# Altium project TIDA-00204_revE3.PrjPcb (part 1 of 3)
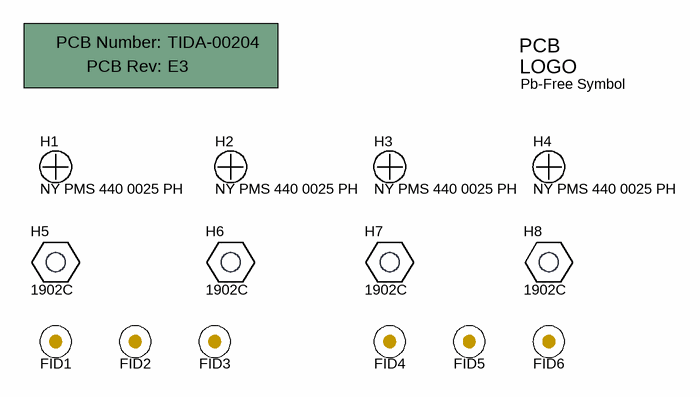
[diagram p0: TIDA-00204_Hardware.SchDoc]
CopyrightYear: 2017; EVM_Orderable: N/A; PCB_Layout: Klaus Hacker; PCB_Rev: E3; PRJ_Customer: TI Confidential - NDA; PRJ_Engineer: Texas Instruments; PRJ_Number: TIDA-00204; PRJ_Title: EMI Compliant Dual Port Industrial Gigabit Ethernet PHY; SCH_Rev: E3; TechSupport: http://www.ti.com/support
10 sheets, 537 parts. Net scope: global (net labels, ports and power ports of the same name join across sheets).
Board file: TIDA-00204_revE3_PCB.PcbDoc
Sheets:
  TIDA-00204_Hardware.SchDoc
  TIDA-00204_revE3_JTAGUSB.SchDoc
  TIDA-00204_revE3_Memory.SchDoc
  TIDA-00204_revE3_PHY_1.SchDoc
  TIDA-00204_revE3_PHY_2.SchDoc
  TIDA-00204_revE3_PS_0.SchDoc
  TIDA-00204_revE3_PS_1.SchDoc
  TIDA-00204_revE3_PS_2.SchDoc
  TIDA-00204_revE3_Sitara_PS.SchDoc
  TIDA-00204_revE3_Sitara_SC_0.SchDoc

## Sheet TIDA-00204_Hardware.SchDoc: =DocumentName
size 431 x 279 mm; Date: Not shown in title block; ApprovedBy: Not shown in title block; CheckedBy: Not shown in title block; Author: Not shown in title block; CompanyName: Not shown in title block; DrawnBy: K. Mogensen; Engineer: K. Mogensen; Organization: Not shown in title block; Address1: Not shown in title block; Address2: Not shown in title block; Address3: Not shown in title block; Address4: Not shown in title block; DocumentNumber: 10; Revision: Use project parameter SCH_Rev; SheetNumber: 10; SheetTotal: 10; PageSetup: Record=PageOptions¦CenterHorizontal=True¦CenterVertical=True¦PrintScale=1.00¦XCorrection=1.00¦YCorrection=1.00¦PrintKind=0¦BorderSize=5000000¦LeftOffset=0¦BottomOffset=0¦Orientation=2¦PaperLength=1000¦PaperWidth=1000¦Scale=100¦PaperSource=15¦PrintQuality=600¦MediaType=1¦DitherType=10¦PaperKind=Letter¦PrintScaleMode=1

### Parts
!PCB1  Printed Circuit Board  (value not drawn)  (mechanical)
FID1  Fiducial  [Fiducial10-20]  (value not drawn)  (no BOM)
FID2  Fiducial  [Fiducial10-20]  (value not drawn)  (no BOM)
FID3  Fiducial  [Fiducial10-20]  (value not drawn)  (no BOM)
FID4  Fiducial  [Fiducial10-20]  (value not drawn)  (no BOM)
FID5  Fiducial  [Fiducial10-20]  (value not drawn)  (no BOM)
FID6  Fiducial  [Fiducial10-20]  (value not drawn)  (no BOM)
H1  NY PMS 440 0025 PH  [NY PMS 440 0025 PH]
H2  NY PMS 440 0025 PH  [NY PMS 440 0025 PH]
H3  NY PMS 440 0025 PH  [NY PMS 440 0025 PH]
H4  NY PMS 440 0025 PH  [NY PMS 440 0025 PH]
H5  1902C  [Keystone_1902C]
H6  1902C  [Keystone_1902C]
H7  1902C  [Keystone_1902C]
H8  1902C  [Keystone_1902C]
Logo2  Pb-Free Symbol  [Pb-Free_Overlay_Small]  (no BOM)

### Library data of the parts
!PCB1 = PCB: Manufacturer: Any; PartNumber: TIDA-00204; SymbolCreator: a0412235
FID1-FID6 = Fiducial: Fiducial mark.  There is nothing to buy or mount.; SymbolCreator: codlsc
H1-H4 = NY PMS 440 0025 PH: Machine Screw, Round, #4-40 x 1/4, Nylon, Philips panhead; Manufacturer: B&F Fastener Supply; CompType: Hardware; SymbolCreator: codlsc; U/M: EA
H5-H8 = 1902C: Standoff, Hex, 0.5"L #4-40 Nylon; Manufacturer: Keystone; CompType: Hardware
Logo2 = Pb-Free: SymbolCreator: a0412235

## Sheet TIDA-00204_revE3_JTAGUSB.SchDoc: =DocumentName
size 431 x 279 mm; Date: Not shown in title block; ApprovedBy: Not shown in title block; CheckedBy: Not shown in title block; Author: Not shown in title block; CompanyName: Not shown in title block; DrawnBy: K. Mogensen; Engineer: K. Mogensen; Organization: Not shown in title block; Address1: Not shown in title block; Address2: Not shown in title block; Address3: Not shown in title block; Address4: Not shown in title block; DocumentNumber: 9; Revision: Use project parameter SCH_Rev; SheetNumber: 9; SheetTotal: 10; PageSetup: Record=PageOptions¦CenterHorizontal=True¦CenterVertical=True¦PrintScale=0.62¦XCorrection=1.00¦YCorrection=1.00¦PrintKind=0¦BorderSize=5000000¦LeftOffset=0¦BottomOffset=0¦Orientation=2¦PaperLength=1000¦PaperWidth=1000¦Scale=100¦PaperSource=15¦PrintQuality=600¦MediaType=1¦DitherType=10¦PaperKind=Letter¦PrintScaleMode=1
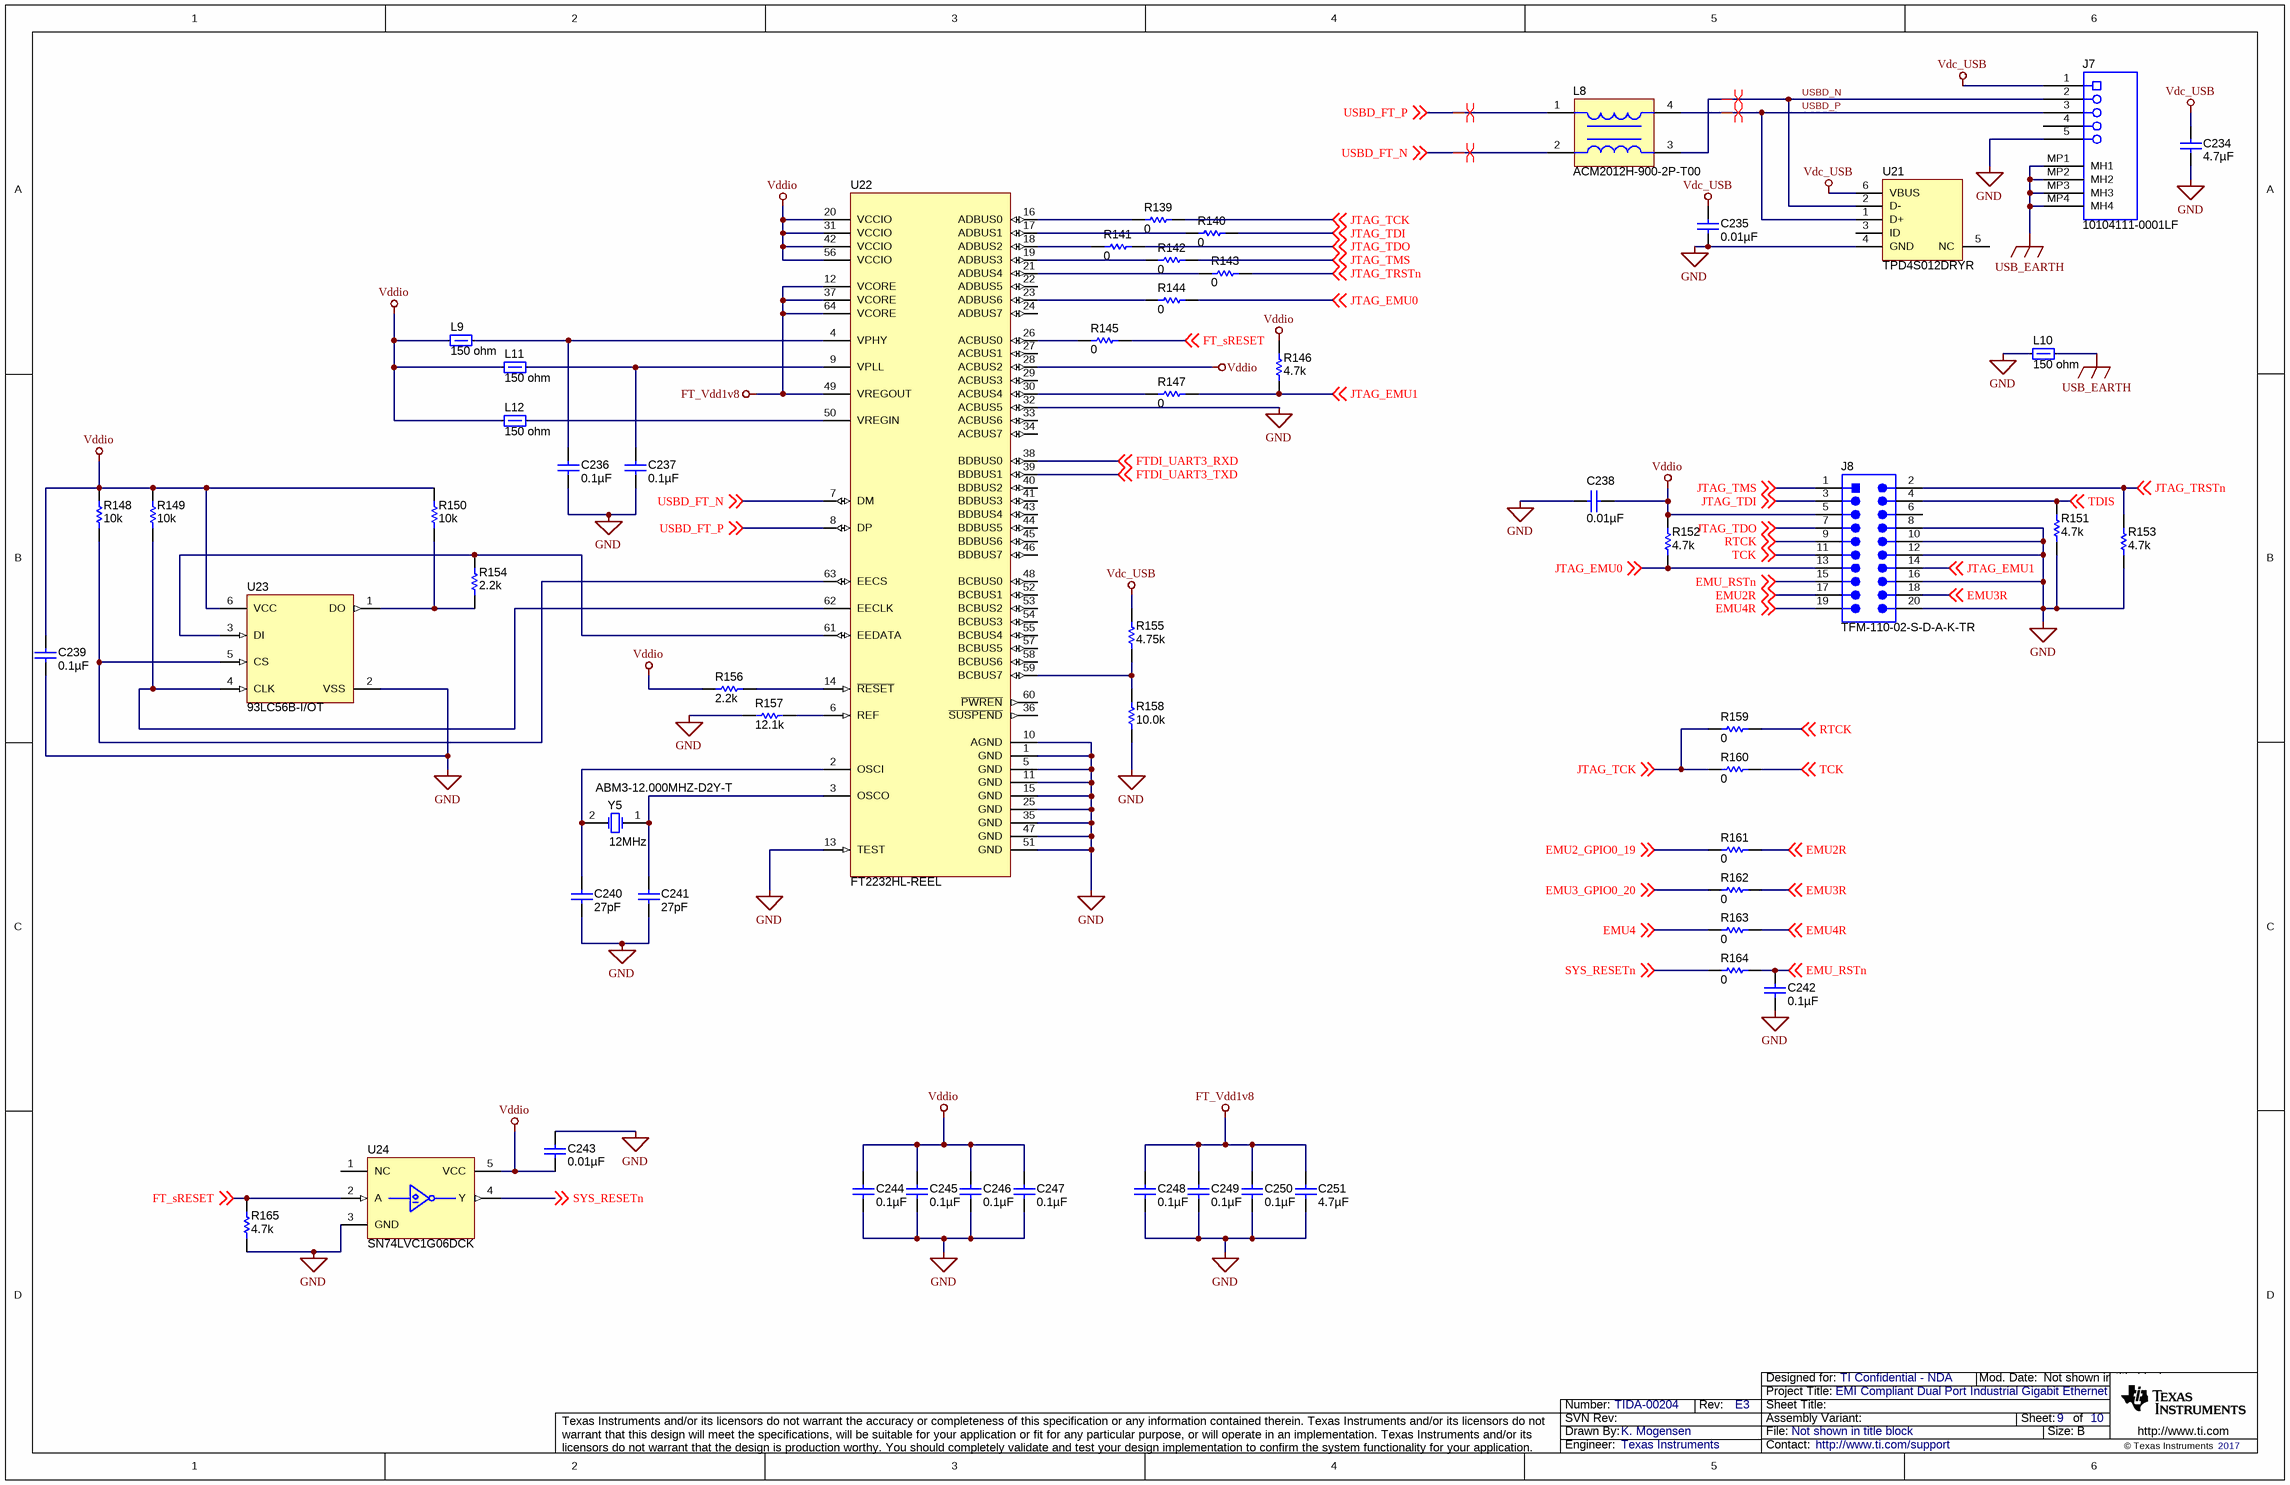
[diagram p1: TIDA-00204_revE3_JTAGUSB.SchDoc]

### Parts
C234  ValueDisplayed: 4.7µF  [0603]  (hidden comment: GRM188R61C475KAAJ)
C235  ValueDisplayed: 0.01µF  [0201]  (hidden comment: GRM033R71A103KA01D)
C236  ValueDisplayed: 0.1µF  [0402]  (hidden comment: GRM155R71A104KA01D)
C237  ValueDisplayed: 0.1µF  [0402]  (hidden comment: GRM155R71A104KA01D)
C238  ValueDisplayed: 0.01µF  [0201]  (hidden comment: GRM033R71A103KA01D)
C239  ValueDisplayed: 0.1µF  [0402]  (hidden comment: GRM155R71A104KA01D)
C240  ValueDisplayed: 27pF  [0402]  (hidden comment: GRM1555C1H270JA01D)
C241  ValueDisplayed: 27pF  [0402]  (hidden comment: GRM1555C1H270JA01D)
C242  ValueDisplayed: 0.1µF  [0402]  (hidden comment: GRM155R71A104KA01D)
C243  ValueDisplayed: 0.01µF  [0201]  (hidden comment: GRM033R71A103KA01D)
C244  ValueDisplayed: 0.1µF  [0402]  (hidden comment: GRM155R71A104KA01D)
C245  ValueDisplayed: 0.1µF  [0402]  (hidden comment: GRM155R71A104KA01D)
C246  ValueDisplayed: 0.1µF  [0402]  (hidden comment: GRM155R71A104KA01D)
C247  ValueDisplayed: 0.1µF  [0402]  (hidden comment: GRM155R71A104KA01D)
C248  ValueDisplayed: 0.1µF  [0402]  (hidden comment: GRM155R71A104KA01D)
C249  ValueDisplayed: 0.1µF  [0402]  (hidden comment: GRM155R71A104KA01D)
C250  ValueDisplayed: 0.1µF  [0402]  (hidden comment: GRM155R71A104KA01D)
C251  ValueDisplayed: 4.7µF  [0603]  (hidden comment: GRM188R61C475KAAJ)
J7  10104111-0001LF  [FCI_10104111-0001LF]
J8  TFM-110-02-S-D-A-K-TR  [Samtec_TFM-110-02-S-D-A-K]
L8  ACM2012H-900-2P-T00  [TDK_ACM2012H-900-2P-T00]
L9  value 150 ohm  [0805_HV]  (hidden comment: LI0805H151R-10)
L10  value 150 ohm  [0805_HV]  (hidden comment: LI0805H151R-10)
L11  value 150 ohm  [0805_HV]  (hidden comment: LI0805H151R-10)
L12  value 150 ohm  [0805_HV]  (hidden comment: LI0805H151R-10)
R139  ValueDisplayed: 0  [0603]  (hidden comment: CRCW06030000Z0EA)
R140  ValueDisplayed: 0  [0603]  (hidden comment: CRCW06030000Z0EA)
R141  ValueDisplayed: 0  [0603]  (hidden comment: CRCW06030000Z0EA)
R142  ValueDisplayed: 0  [0603]  (hidden comment: CRCW06030000Z0EA)
R143  ValueDisplayed: 0  [0603]  (hidden comment: CRCW06030000Z0EA)
R144  ValueDisplayed: 0  [0603]  (hidden comment: CRCW06030000Z0EA)
R145  ValueDisplayed: 0  [0603]  (hidden comment: CRCW06030000Z0EA)
R146  ValueDisplayed: 4.7k  [0402]  (hidden comment: CRCW04024K70JNED)
R147  ValueDisplayed: 0  [0603]  (hidden comment: CRCW06030000Z0EA)
R148  ValueDisplayed: 10k  [0402]  (hidden comment: CRCW040210K0JNED)
R149  ValueDisplayed: 10k  [0402]  (hidden comment: CRCW040210K0JNED)
R150  ValueDisplayed: 10k  [0402]  (hidden comment: CRCW040210K0JNED)
R151  ValueDisplayed: 4.7k  [0402]  (hidden comment: CRCW04024K70JNED)
R152  ValueDisplayed: 4.7k  [0402]  (hidden comment: CRCW04024K70JNED)
R153  ValueDisplayed: 4.7k  [0402]  (hidden comment: CRCW04024K70JNED)
R154  ValueDisplayed: 2.2k  [0402]  (hidden comment: CRCW04022K20JNED)
R155  ValueDisplayed: 4.75k  [0402]  (hidden comment: CRCW04024K75FKED)
R156  ValueDisplayed: 2.2k  [0402]  (hidden comment: CRCW04022K20JNED)
R157  ValueDisplayed: 12.1k  [0402]  (hidden comment: CRCW040212K1FKED)
R158  ValueDisplayed: 10.0k  [0402]  (hidden comment: CRCW040210K0FKED)
R159  ValueDisplayed: 0  [0603]  (hidden comment: CRCW06030000Z0EA)
R160  ValueDisplayed: 0  [0603]  (hidden comment: CRCW06030000Z0EA)
R161  ValueDisplayed: 0  [0603]  (hidden comment: CRCW06030000Z0EA)
R162  ValueDisplayed: 0  [0603]  (hidden comment: CRCW06030000Z0EA)
R163  ValueDisplayed: 0  [0603]  (hidden comment: CRCW06030000Z0EA)
R164  ValueDisplayed: 0  [0603]  (hidden comment: CRCW06030000Z0EA)
R165  ValueDisplayed: 4.7k  [0402]  (hidden comment: CRCW04024K70JNED)
U21  TPD4S012DRYR  [DRY0006A]
U22  FT2232HL-REEL  [LQFP64_N]
U23  93LC56B-I/OT  [SOT-23-6]
U24  SN74LVC1G06DCK  [DCK0005A_N]
Y5  ABM3-12.000MHZ-D2Y-T  Frequency: 12MHz  [XTAL_ABM3]

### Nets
FT_Vdd1v8: C248.2 C249.2 C250.2 C251.1 U22.12(VCORE) U22.37(VCORE) U22.49(VREGOUT) U22.64(VCORE)
GND: C234.2 C235.2 C236.1 C237.1 C238.1 C239.1 C240.2 C241.2 C242.1 C243.1 C244.1 C245.1 C246.1 C247.1 C248.1 C249.1 C250.1 C251.2 J7.5 J8.8 J8.10 J8.12 J8.16 J8.20 L10.1 R151.1 R153.1 R157.1 R158.1 R165.1 U21.4(GND) U22.1(GND) U22.5(GND) U22.10(AGND) U22.11(GND) U22.13(TEST) U22.15(GND) U22.25(GND) U22.32(ACBUS5) U22.35(GND) U22.47(GND) U22.51(GND) U23.2(VSS) U24.3(GND)
USB_EARTH: J7.MP1(MH1) J7.MP2(MH2) J7.MP3(MH3) J7.MP4(MH4) L10.2
Vdc_USB: C234.1 C235.1 J7.1 R155.2 U21.6(VBUS)
Vddio: C238.2 C239.2 C243.2 C244.2 C245.2 C246.2 C247.2 J8.5 L9.1 L11.1 L12.1 R146.2 R148.2 R149.2 R150.2 R152.2 R156.2 U22.20(VCCIO) U22.28(ACBUS2) U22.31(VCCIO) U22.42(VCCIO) U22.56(VCCIO) U23.6(VCC) U24.5(VCC)
EMU2_GPIO0_19: R161.1 ; off-sheet EMU2_GPIO0_19
EMU2R: J8.17 R161.2 ; off-sheet EMU2R
EMU3_GPIO0_20: R162.1 ; off-sheet EMU3_GPIO0_20
EMU3R: J8.18 R162.2 ; off-sheet EMU3R
EMU4: R163.1 ; off-sheet EMU4
EMU4R: J8.19 R163.2 ; off-sheet EMU4R
EMU_RSTn: C242.2 J8.15 R164.2 ; off-sheet EMU_RSTn
FT_sRESET: R145.2 R165.2 U24.2(A) ; off-sheet FT_sRESET
FTDI_UART3_RXD: U22.38(BDBUS0) ; off-sheet FTDI_UART3_RXD
FTDI_UART3_TXD: U22.39(BDBUS1) ; off-sheet FTDI_UART3_TXD
JTAG_EMU0: J8.13 R144.2 R152.1 ; off-sheet JTAG_EMU0
JTAG_EMU1: J8.14 R146.1 R147.2 ; off-sheet JTAG_EMU1
JTAG_TCK: R139.2 R159.1 R160.1 ; off-sheet JTAG_TCK
JTAG_TDI: J8.3 R140.2 ; off-sheet JTAG_TDI
JTAG_TDO: J8.7 R141.2 ; off-sheet JTAG_TDO
JTAG_TMS: J8.1 R142.2 ; off-sheet JTAG_TMS
JTAG_TRSTn: J8.2 R143.2 R153.2 ; off-sheet JTAG_TRSTn
RTCK: J8.9 R159.2 ; off-sheet RTCK
SYS_RESETn: R164.1 U24.4(Y) ; off-sheet SYS_RESETn
TCK: J8.11 R160.2 ; off-sheet TCK
TDIS: J8.4 R151.2 ; off-sheet TDIS
USBD_FT_N: L8.2 U22.7(DM) ; off-sheet USBD_FT_N
USBD_FT_P: L8.1 U22.8(DP) ; off-sheet USBD_FT_P
USBD_N: J7.2 L8.3 U21.2(D-)
USBD_P: J7.3 L8.4 U21.1(D+)
NetC236_2: C236.2 L9.2 U22.4(VPHY)
NetC237_2: C237.2 L11.2 U22.9(VPLL)
NetC240_1: C240.1 U22.2(OSCI) Y5.2(OSC2)
NetC241_1: C241.1 U22.3(OSCO) Y5.1(OSC1)
NetL12_2: L12.2 U22.50(VREGIN)
NetR139_1: R139.1 U22.16(ADBUS0)
NetR140_1: R140.1 U22.17(ADBUS1)
NetR141_1: R141.1 U22.18(ADBUS2)
NetR142_1: R142.1 U22.19(ADBUS3)
NetR143_1: R143.1 U22.21(ADBUS4)
NetR144_1: R144.1 U22.23(ADBUS6)
NetR145_1: R145.1 U22.26(ACBUS0)
NetR147_1: R147.1 U22.30(ACBUS4)
NetR148_1: R148.1 U22.63(EECS) U23.5(CS)
NetR149_1: R149.1 U22.62(EECLK) U23.4(CLK)
NetR150_1: R150.1 R154.1 U23.1(DO)
NetR154_2: R154.2 U22.61(EEDATA) U23.3(DI)
NetR155_1: R155.1 R158.2 U22.59(BCBUS7)
NetR156_1: R156.1 U22.14(~{RESET})
NetR157_2: R157.2 U22.6(REF)

Not connected (* = marked no-connect by the designer): J7 4; J8 6; U21 3(ID) 5(NC); U22 22(ADBUS5) 24(ADBUS7) 27(ACBUS1) 29(ACBUS3) 33(ACBUS6) 34(ACBUS7) 36(~{SUSPEND}) 40(BDBUS2) 41(BDBUS3) 43(BDBUS4) 44(BDBUS5) 45(BDBUS6) 46(BDBUS7) 48(BCBUS0) 52(BCBUS1) 53(BCBUS2) 54(BCBUS3) 55(BCBUS4) 57(BCBUS5) 58(BCBUS6) 60(~{PWREN}); U24 1(NC)

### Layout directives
differential pair: USBD_FT_N, USBD_FT_P, USBD_N, USBD_P

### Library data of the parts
C234 C251 = GRM188R61C475KAAJ: CAP, CERM, 4.7 µF, 16 V, +/- 10%, X5R, 0603; Manufacturer: MuRata; Polarized: N; CompType: Capacitor; Value: 4.7uF; U/M: EA; Cap_F: 0.0000047; Tolerance_%: 10; Value1: Unknown; VDC_V: 16; Value2: 16V; TaMin_C: -55; TaMax_C: 85
C235 C238 C243 = GRM033R71A103KA01D: CAP, CERM, 0.01 µF, 10 V, +/- 10%, X7R, 0201; Manufacturer: MuRata; Polarized: N; CompType: Capacitor; Value: 0.01uF; U/M: EA; Cap_F: 0.00000001; Tolerance_%: 10; Value1: Unknown; Value2: 10V; TaMin_C: -55; TaMax_C: 125
C236 C237 C239 C242 C244-C250 = GRM155R71A104KA01D: CAP, CERM, 0.1 µF, 10 V, +/- 10%, X7R, 0402; Manufacturer: MuRata; Polarized: N; CompType: Capacitor; Value: 0.1uF; U/M: EA; Cap_F: 0.0000001; Tolerance_%: 10; Value1: Unknown; Value2: 10V; TaMin_C: -55; TaMax_C: 125
C240 C241 = GRM1555C1H270JA01D: CAP, CERM, 27 pF, 50 V, +/- 5%, C0G/NP0, 0402; Manufacturer: MuRata; Polarized: N; CompType: Capacitor; Value: 27pF; U/M: EA; Cap_F: 0.000000000027; Tolerance_%: 5; Value1: Unknown; VDC_V: 50; Value2: 50V; TaMin_C: -55; TaMax_C: 125
J7 = 10104111-0001LF: Receptacle, 0.65 mm, 5x1, Gold, R/A, SMT; Manufacturer: FCI; SymbolCreator: Altium; U/M: EA
J8 = TFM-110-02-S-D-A-K-TR: CONN SHRD HDR HDR 20 POS 1.27MM SLDR ST SMD; Manufacturer: Samtec; SymbolCreator: a0412235; CompType: Header; U/M: EA
L8 = ACM2012H-900-2P-T00: Common Mode Filter, 90 Ohm, 6 GHz, SMD; Manufacturer: TDK; SymbolCreator: Altium; Value: 90Ohm
L9-L12 = LI0805H151R-10: Ferrite Bead, 150 ohm @ 100 MHz, 0.8 A, 0805; Manufacturer: Laird-Signal Integrity Products; Imax_A: 0.8; DCR_ohm: 0.15; Value1: 0.15 ohm; Value2: 0.8A; ZTyp@100MHz_Ohm: 150
R139-R145 R147 R159-R164 = CRCW06030000Z0EA: RES, 0, 5%, 0.1 W, 0603; Manufacturer: Vishay-Dale; CompType: Resistor; Value: 0; Value_Code: 0000; Tolerance_%: 5; Power_W: 0.1; Value2: 0.1W; VDC_V: 75; TempCo: 200 ppm/C; EIA_Code: E24; U/M: EA
R146 R151-R153 R165 = CRCW04024K70JNED: RES, 4.7 k, 5%, 0.063 W, 0402; Manufacturer: Vishay-Dale; CompType: Resistor; Value: 4.7k; Res_ohm: 4700; Value_Code: 4k70; Tolerance_%: 5; Power_W: 0.063; Value2: 0.063W; VDC_V: 50; TempCo: 200 ppm/C; EIA_Code: E24; U/M: EA
R148-R150 = CRCW040210K0JNED: RES, 10 k, 5%, 0.063 W, 0402; Manufacturer: Vishay-Dale; CompType: Resistor; Value: 10k; Res_ohm: 10000; Value_Code: 10k0; Tolerance_%: 5; Power_W: 0.063; Value2: 0.063W; VDC_V: 50; TempCo: 200 ppm/C; EIA_Code: E24; U/M: EA
R154 R156 = CRCW04022K20JNED: RES, 2.2 k, 5%, 0.063 W, 0402; Manufacturer: Vishay-Dale; CompType: Resistor; Value: 2.2k; Res_ohm: 2200; Value_Code: 2k20; Tolerance_%: 5; Power_W: 0.063; Value2: 0.063W; VDC_V: 50; TempCo: 200 ppm/C; EIA_Code: E24; U/M: EA
R155 = CRCW04024K75FKED: RES, 4.75 k, 1%, 0.063 W, 0402; Manufacturer: Vishay-Dale; CompType: Resistor; Value: 4.75k; Res_ohm: 4750; Value_Code: 4k75; Tolerance_%: 1; Power_W: 0.063; Value2: 0.063W; VDC_V: 50; TempCo: 100 ppm/C; EIA_Code: E96; U/M: EA
R157 = CRCW040212K1FKED: RES, 12.1 k, 1%, 0.063 W, 0402; Manufacturer: Vishay-Dale; CompType: Resistor; Value: 12.1k; Res_ohm: 12100; Value_Code: 12k1; Tolerance_%: 1; Power_W: 0.063; Value2: 0.063W; VDC_V: 50; TempCo: 100 ppm/C; EIA_Code: E96; U/M: EA
R158 = CRCW040210K0FKED: RES, 10.0 k, 1%, 0.063 W, 0402; Manufacturer: Vishay-Dale; CompType: Resistor; Value: 10.0k; Res_ohm: 10000; Value_Code: 10k0; Tolerance_%: 1; Power_W: 0.063; Value2: 0.063W; VDC_V: 50; TempCo: 100 ppm/C; EIA_Code: E96; U/M: EA
U21 = TPD4S012DRYR: USB ESD Solution with Power Clamp, 4 Channels, -40 to +85 degC, 6-pin SON (DRY), Green (RoHS & no Sb/Br); Manufacturer: Texas Instruments; Alternate Manufacturer: None; Alternate PartNumber: Equivalent; Breakdown Voltage(Min)(V): 6; IEC 61000-4-2 Air-Gap(+/- kV): 10; IO Capacitance(Typ)(pF): 0.8; USB High Speed: TRUE
U22 = FT2232HL-REEL: Dual High Speed USB To Multipurpose UART/FIFO IC, LQFP-64; Manufacturer: FTDI; SymbolCreator: Altium
U23 = 93LC56B-I/OT: 2K Microwire Compatible Serial EEPROM, SOT-23-6; Manufacturer: Microchip; SymbolCreator: x0208326
U24 = SN74LVC1G06DCK: Single Inverter Buffer/Driver With Open-Drain Output, DCK0005A; Alternate Manufacturer: None; Manufacturer: Texas Instruments; SymbolCreator: a0411947; CompType: IC; U/M: EA
Y5 = ABM3-12.000MHZ-D2Y-T: Crystal, 12 MHz, 18 pF, SMD; Manufacturer: Abracon Corportation; SymbolCreator: a0412235; U/M: EA; TaMin_C: -40; TaMax_C: 85; Frequency Stability: ±30ppm

## Sheet TIDA-00204_revE3_Memory.SchDoc: =DocumentName
size 431 x 279 mm; Date: Not shown in title block; ApprovedBy: Not shown in title block; CheckedBy: Not shown in title block; Author: Not shown in title block; CompanyName: Not shown in title block; DrawnBy: K. Mogensen; Engineer: K. Mogensen; Organization: Not shown in title block; Address1: Not shown in title block; Address2: Not shown in title block; Address3: Not shown in title block; Address4: Not shown in title block; DocumentNumber: 8; Revision: Use project parameter SCH_Rev; SheetNumber: 8; SheetTotal: 10; PageSetup: Record=PageOptions¦CenterHorizontal=True¦CenterVertical=True¦PrintScale=0.62¦XCorrection=1.00¦YCorrection=1.00¦PrintKind=0¦BorderSize=5000000¦LeftOffset=0¦BottomOffset=0¦Orientation=2¦PaperLength=1000¦PaperWidth=1000¦Scale=100¦PaperSource=15¦PrintQuality=600¦MediaType=1¦DitherType=10¦PaperKind=Letter¦PrintScaleMode=1
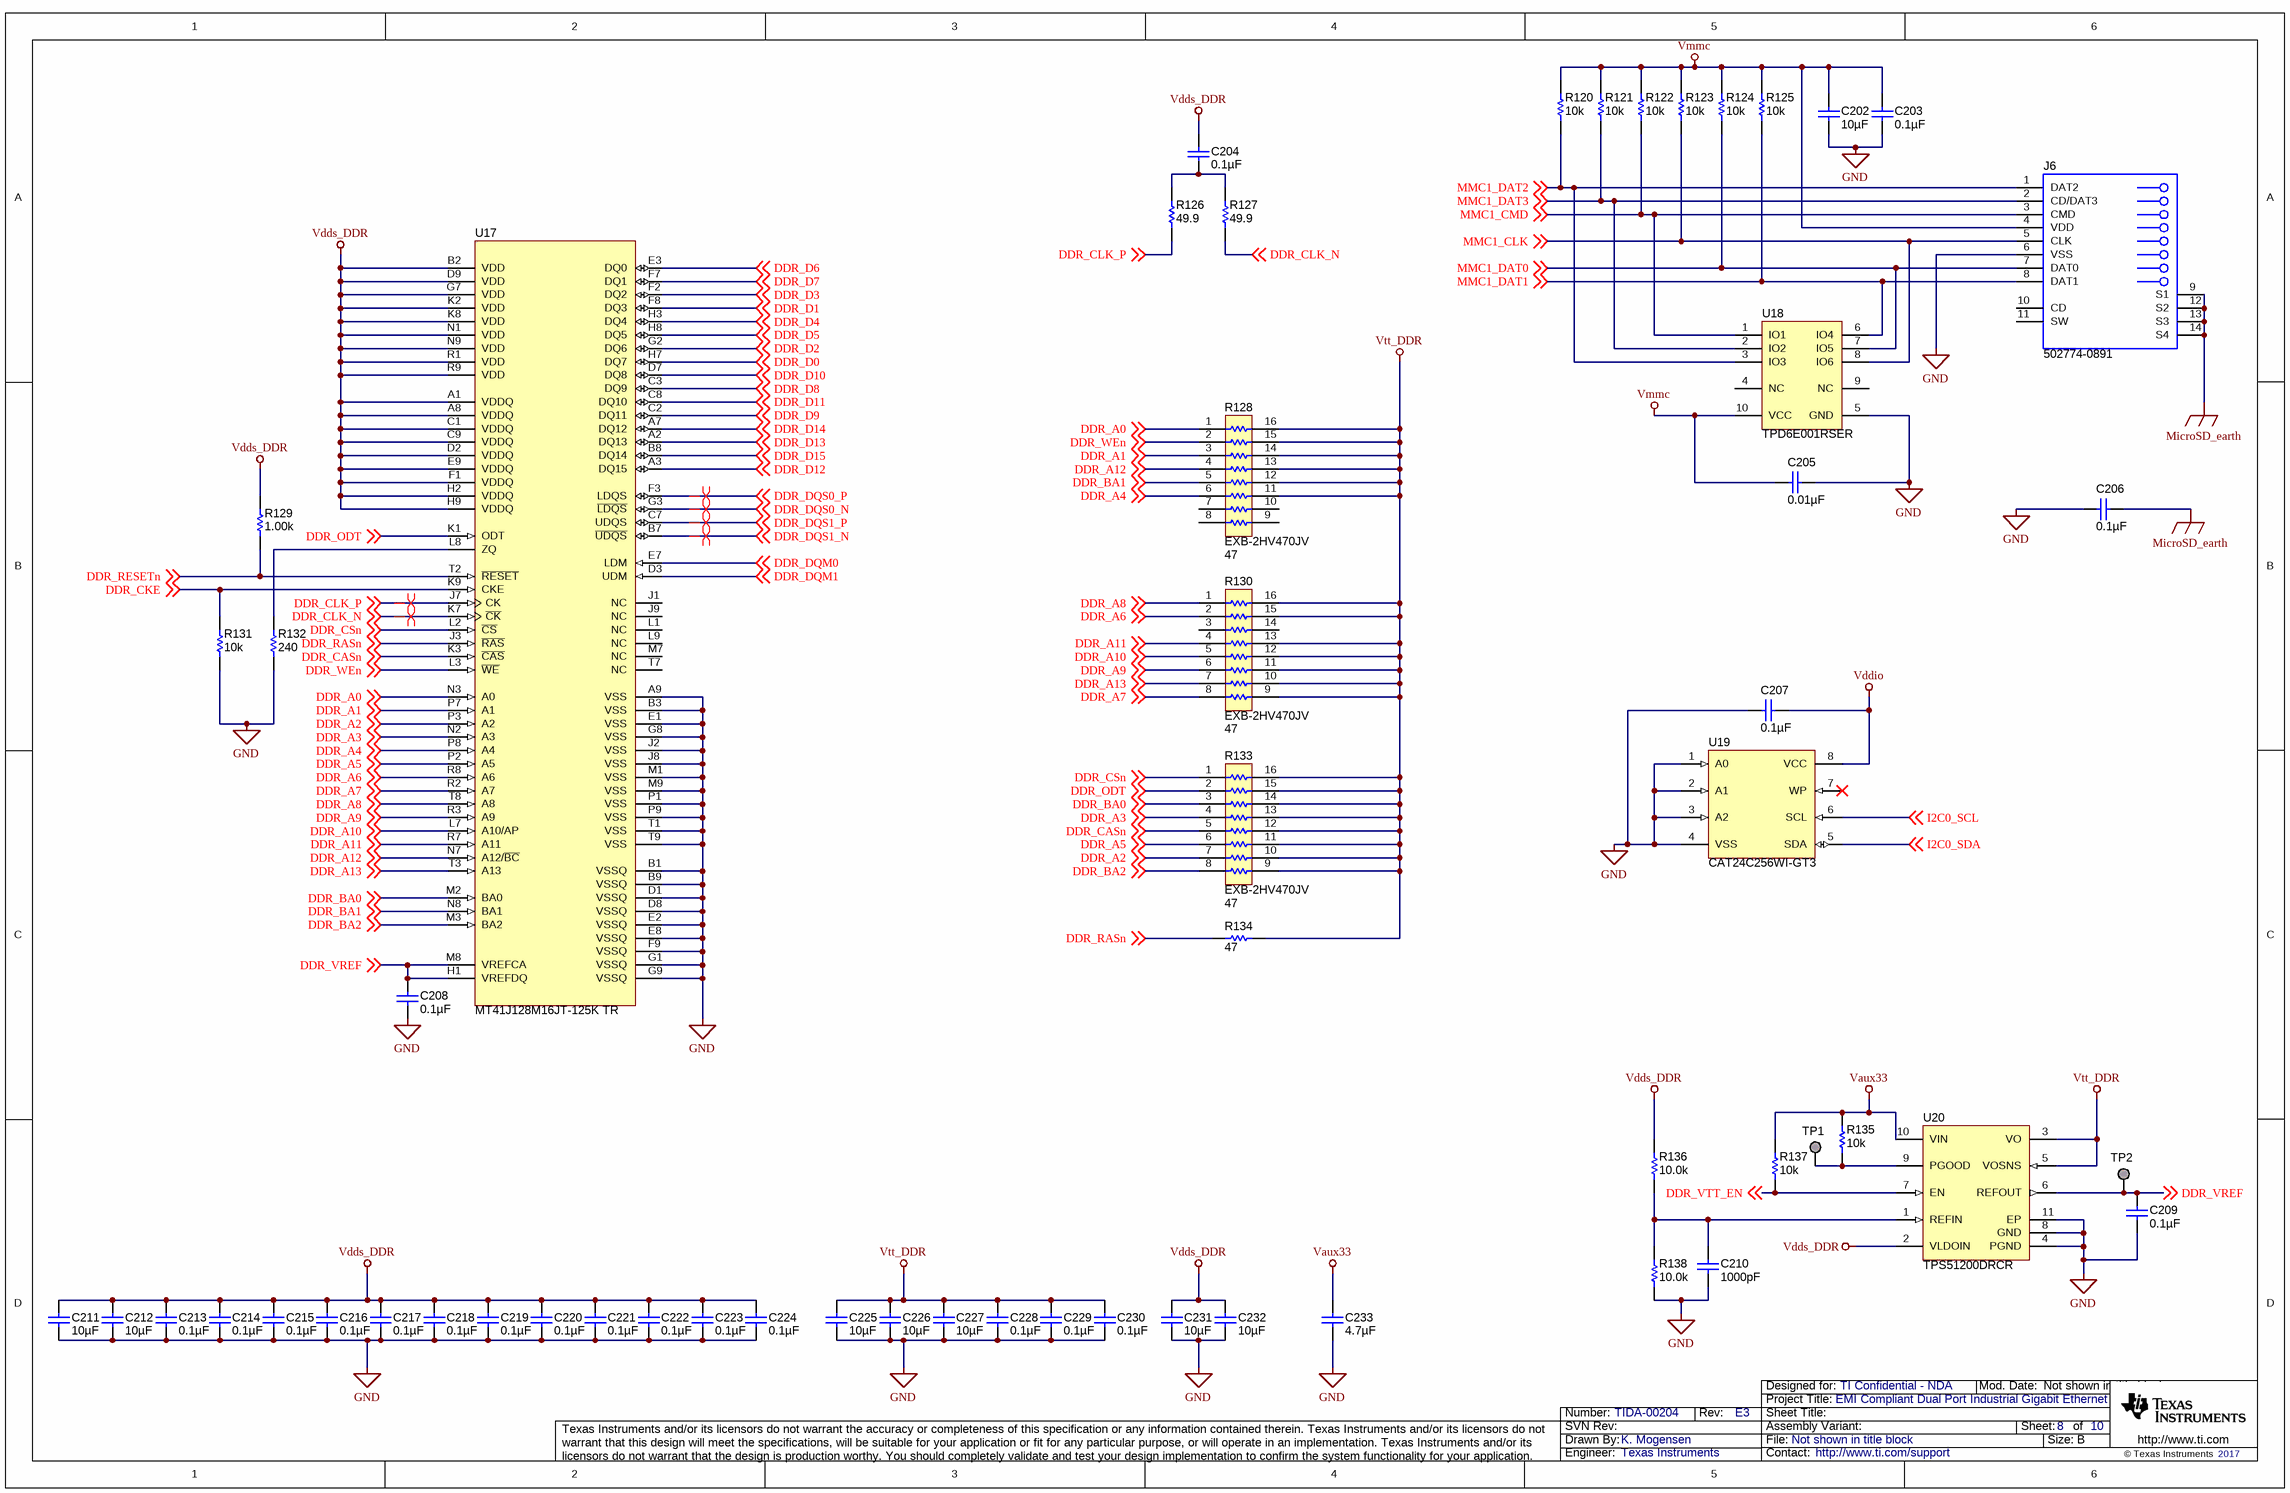
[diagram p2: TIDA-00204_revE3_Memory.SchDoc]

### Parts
C202  ValueDisplayed: 10µF  [0603]  (hidden comment: C1608X5R1E106M080AC)
C203  ValueDisplayed: 0.1µF  [0402]  (hidden comment: GRM155R71A104KA01D)
C204  ValueDisplayed: 0.1µF  [0402]  (hidden comment: GRM155R71A104KA01D)
C205  ValueDisplayed: 0.01µF  [0201]  (hidden comment: GRM033R71A103KA01D)
C206  ValueDisplayed: 0.1µF  [0402]  (hidden comment: GRM155R71C104KA88D)
C207  ValueDisplayed: 0.1µF  [0402]  (hidden comment: GRM155R71A104KA01D)
C208  ValueDisplayed: 0.1µF  [0201]  (hidden comment: CL03A104KP3NNNC)
C209  ValueDisplayed: 0.1µF  [0402]  (hidden comment: GRM155R71A104KA01D)
C210  ValueDisplayed: 1000pF  [0201]  (hidden comment: GRM033R71C102KA01D)
C211  ValueDisplayed: 10µF  [0603]  (hidden comment: C1608X5R1E106M080AC)
C212  ValueDisplayed: 10µF  [0603]  (hidden comment: C1608X5R1E106M080AC)
C213  ValueDisplayed: 0.1µF  [0201]  (hidden comment: CL03A104KP3NNNC)
C214  ValueDisplayed: 0.1µF  [0201]  (hidden comment: CL03A104KP3NNNC)
C215  ValueDisplayed: 0.1µF  [0201]  (hidden comment: CL03A104KP3NNNC)
C216  ValueDisplayed: 0.1µF  [0201]  (hidden comment: CL03A104KP3NNNC)
C217  ValueDisplayed: 0.1µF  [0201]  (hidden comment: CL03A104KP3NNNC)
C218  ValueDisplayed: 0.1µF  [0201]  (hidden comment: CL03A104KP3NNNC)
C219  ValueDisplayed: 0.1µF  [0201]  (hidden comment: CL03A104KP3NNNC)
C220  ValueDisplayed: 0.1µF  [0201]  (hidden comment: CL03A104KP3NNNC)
C221  ValueDisplayed: 0.1µF  [0201]  (hidden comment: CL03A104KP3NNNC)
C222  ValueDisplayed: 0.1µF  [0201]  (hidden comment: CL03A104KP3NNNC)
C223  ValueDisplayed: 0.1µF  [0201]  (hidden comment: CL03A104KP3NNNC)
C224  ValueDisplayed: 0.1µF  [0201]  (hidden comment: CL03A104KP3NNNC)
C225  ValueDisplayed: 10µF  [0603]  (hidden comment: C1608X5R1E106M080AC)
C226  ValueDisplayed: 10µF  [0603]  (hidden comment: C1608X5R1E106M080AC)
C227  ValueDisplayed: 10µF  [0603]  (hidden comment: C1608X5R1E106M080AC)
C228  ValueDisplayed: 0.1µF  [0201]  (hidden comment: CL03A104KP3NNNC)
C229  ValueDisplayed: 0.1µF  [0201]  (hidden comment: CL03A104KP3NNNC)
C230  ValueDisplayed: 0.1µF  [0201]  (hidden comment: CL03A104KP3NNNC)
C231  ValueDisplayed: 10µF  [0603]  (hidden comment: C1608X5R1E106M080AC)
C232  ValueDisplayed: 10µF  [0603]  (hidden comment: C1608X5R1E106M080AC)
C233  ValueDisplayed: 4.7µF  [0603]  (hidden comment: GRM188R61C475KAAJ)
J6  502774-0891  [Molex_502774-0891]
R120  ValueDisplayed: 10k  [0402]  (hidden comment: CRCW040210K0JNED)
R121  ValueDisplayed: 10k  [0402]  (hidden comment: CRCW040210K0JNED)
R122  ValueDisplayed: 10k  [0402]  (hidden comment: CRCW040210K0JNED)
R123  ValueDisplayed: 10k  [0402]  (hidden comment: CRCW040210K0JNED)
R124  ValueDisplayed: 10k  [0402]  (hidden comment: CRCW040210K0JNED)
R125  ValueDisplayed: 10k  [0402]  (hidden comment: CRCW040210K0JNED)
R126  ValueDisplayed: 49.9  [0402]  (hidden comment: CRCW040249R9FKED)
R127  ValueDisplayed: 49.9  [0402]  (hidden comment: CRCW040249R9FKED)
R128  EXB-2HV470JV  ValueDisplayed: 47  [RESCAXS_EXB-2HV]
R129  ValueDisplayed: 1.00k  [0402]  (hidden comment: CRCW04021K00FKED)
R130  EXB-2HV470JV  ValueDisplayed: 47  [RESCAXS_EXB-2HV]
R131  ValueDisplayed: 10k  [0402]  (hidden comment: CRCW040210K0JNED)
R132  ValueDisplayed: 240  [0402]  (hidden comment: CRCW0402240RJNED)
R133  EXB-2HV470JV  ValueDisplayed: 47  [RESCAXS_EXB-2HV]
R134  ValueDisplayed: 47  [0402]  (hidden comment: CRCW040247R0JNED)
R135  ValueDisplayed: 10k  [0402]  (hidden comment: CRCW040210K0JNED)
R136  ValueDisplayed: 10.0k  [0402]  (hidden comment: CRCW040210K0FKED)
R137  ValueDisplayed: 10k  [0402]  (hidden comment: CRCW040210K0JNED)
R138  ValueDisplayed: 10.0k  [0402]  (hidden comment: CRCW040210K0FKED)
TP1  TESTPOINT  [OXLEY_SMOX_060_B1_LP]  (value not drawn)  (no BOM)
TP2  TESTPOINT  [OXLEY_SMOX_060_B1_LP]  (value not drawn)  (no BOM)
U17  MT41J128M16JT-125K TR  [96-FBGA]
U18  TPD6E001RSER  [RSE0010A]
U19  CAT24C256WI-GT3  [SOIC-8]
U20  TPS51200DRCR  [DRC0010A]

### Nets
GND: C202.2 C203.1 C205.2 C206.2 C207.1 C208.2 C209.2 C210.2 C211.2 C212.2 C213.2 C214.2 C215.2 C216.2 C217.2 C218.2 C219.2 C220.2 C221.2 C222.2 C223.2 C224.2 C225.2 C226.2 C227.2 C228.2 C229.2 C230.2 C231.2 C232.2 C233.2 J6.6(VSS) R131.1 R132.1 R138.1 U17.A9(VSS) U17.B1(VSSQ) U17.B3(VSS) U17.B9(VSSQ) U17.D1(VSSQ) U17.D8(VSSQ) U17.E1(VSS) U17.E2(VSSQ) U17.E8(VSSQ) U17.F9(VSSQ) U17.G1(VSSQ) U17.G8(VSS) U17.G9(VSSQ) U17.J2(VSS) U17.J8(VSS) U17.M1(VSS) U17.M9(VSS) U17.P1(VSS) U17.P9(VSS) U17.T1(VSS) U17.T9(VSS) U18.5(GND) U19.1(A0) U19.2(A1) U19.3(A2) U19.4(VSS) U20.4(PGND) U20.8(GND) U20.11(EP)
MicroSD_earth: C206.1 J6.9(S1) J6.12(S2) J6.13(S3) J6.14(S4)
Vaux33: C233.1 R135.2 R137.2 U20.10(VIN)
Vddio: C207.2 U19.8(VCC)
Vdds_DDR: C204.2 C211.1 C212.1 C213.1 C214.1 C215.1 C216.1 C217.1 C218.1 C219.1 C220.1 C221.1 C222.1 C223.1 C224.1 C231.1 C232.1 R129.2 R136.2 U17.A1(VDDQ) U17.A8(VDDQ) U17.B2(VDD) U17.C1(VDDQ) U17.C9(VDDQ) U17.D2(VDDQ) U17.D9(VDD) U17.E9(VDDQ) U17.F1(VDDQ) U17.G7(VDD) U17.H2(VDDQ) U17.H9(VDDQ) U17.K2(VDD) U17.K8(VDD) U17.N1(VDD) U17.N9(VDD) U17.R1(VDD) U17.R9(VDD) U20.2(VLDOIN)
Vmmc: C202.1 C203.2 C205.1 J6.4(VDD) R120.2 R121.2 R122.2 R123.2 R124.2 R125.2 U18.10(VCC)
Vtt_DDR: C225.1 C226.1 C227.1 C228.1 C229.1 C230.1 R128.11 R128.12 R128.13 R128.14 R128.15 R128.16 R130.9 R130.10 R130.11 R130.12 R130.13 R130.15 R130.16 R133.9 R133.10 R133.11 R133.12 R133.13 R133.14 R133.15 R133.16 R134.2 U20.3(VO) U20.5(VOSNS)
DDR_A0: R128.1 U17.N3(A0) ; off-sheet DDR_A0
DDR_A1: R128.3 U17.P7(A1) ; off-sheet DDR_A1
DDR_A2: R133.7 U17.P3(A2) ; off-sheet DDR_A2
DDR_A3: R133.4 U17.N2(A3) ; off-sheet DDR_A3
DDR_A4: R128.6 U17.P8(A4) ; off-sheet DDR_A4
DDR_A5: R133.6 U17.P2(A5) ; off-sheet DDR_A5
DDR_A6: R130.2 U17.R8(A6) ; off-sheet DDR_A6
DDR_A7: R130.8 U17.R2(A7) ; off-sheet DDR_A7
DDR_A8: R130.1 U17.T8(A8) ; off-sheet DDR_A8
DDR_A9: R130.6 U17.R3(A9) ; off-sheet DDR_A9
DDR_A10: R130.5 U17.L7(A10/AP) ; off-sheet DDR_A10
DDR_A11: R130.4 U17.R7(A11) ; off-sheet DDR_A11
DDR_A12: R128.4 U17.N7(A12/~{BC}) ; off-sheet DDR_A12
DDR_A13: R130.7 U17.T3(A13) ; off-sheet DDR_A13
DDR_BA0: R133.3 U17.M2(BA0) ; off-sheet DDR_BA0
DDR_BA1: R128.5 U17.N8(BA1) ; off-sheet DDR_BA1
DDR_BA2: R133.8 U17.M3(BA2) ; off-sheet DDR_BA2
DDR_CASn: R133.5 U17.K3(~{CAS}) ; off-sheet DDR_CASn
DDR_CKE: R131.2 U17.K9(CKE) ; off-sheet DDR_CKE
DDR_CLK_N: R127.1 U17.K7(~{CK}) ; off-sheet DDR_CLK_N
DDR_CLK_P: R126.1 U17.J7(CK) ; off-sheet DDR_CLK_P
DDR_CSn: R133.1 U17.L2(~{CS}) ; off-sheet DDR_CSn
DDR_D0: U17.H7(DQ7) ; off-sheet DDR_D0
DDR_D1: U17.F8(DQ3) ; off-sheet DDR_D1
DDR_D2: U17.G2(DQ6) ; off-sheet DDR_D2
DDR_D3: U17.F2(DQ2) ; off-sheet DDR_D3
DDR_D4: U17.H3(DQ4) ; off-sheet DDR_D4
DDR_D5: U17.H8(DQ5) ; off-sheet DDR_D5
DDR_D6: U17.E3(DQ0) ; off-sheet DDR_D6
DDR_D7: U17.F7(DQ1) ; off-sheet DDR_D7
DDR_D8: U17.C3(DQ9) ; off-sheet DDR_D8
DDR_D9: U17.C2(DQ11) ; off-sheet DDR_D9
DDR_D10: U17.D7(DQ8) ; off-sheet DDR_D10
DDR_D11: U17.C8(DQ10) ; off-sheet DDR_D11
DDR_D12: U17.A3(DQ15) ; off-sheet DDR_D12
DDR_D13: U17.A2(DQ13) ; off-sheet DDR_D13
DDR_D14: U17.A7(DQ12) ; off-sheet DDR_D14
DDR_D15: U17.B8(DQ14) ; off-sheet DDR_D15
DDR_DQM0: U17.E7(LDM) ; off-sheet DDR_DQM0
DDR_DQM1: U17.D3(UDM) ; off-sheet DDR_DQM1
DDR_DQS0_N: U17.G3(~{LDQS}) ; off-sheet DDR_DQS0_N
DDR_DQS0_P: U17.F3(LDQS) ; off-sheet DDR_DQS0_P
DDR_DQS1_N: U17.B7(~{UDQS}) ; off-sheet DDR_DQS1_N
DDR_DQS1_P: U17.C7(UDQS) ; off-sheet DDR_DQS1_P
DDR_ODT: R133.2 U17.K1(ODT) ; off-sheet DDR_ODT
DDR_RASn: R134.1 U17.J3(~{RAS}) ; off-sheet DDR_RASn
DDR_RESETn: R129.1 U17.T2(~{RESET}) ; off-sheet DDR_RESETn
DDR_VREF: C208.1 C209.1 TP2.1 U17.H1(VREFDQ) U17.M8(VREFCA) U20.6(REFOUT) ; off-sheet DDR_VREF
DDR_VTT_EN: R137.1 U20.7(EN) ; off-sheet DDR_VTT_EN
DDR_WEn: R128.2 U17.L3(~{WE}) ; off-sheet DDR_WEn
I2C0_SCL: U19.6(SCL) ; off-sheet I2C0_SCL
I2C0_SDA: U19.5(SDA) ; off-sheet I2C0_SDA
MMC1_CLK: J6.5(CLK) R123.1 U18.8(IO6) ; off-sheet MMC1_CLK
MMC1_CMD: J6.3(CMD) R122.1 U18.1(IO1) ; off-sheet MMC1_CMD
MMC1_DAT0: J6.7(DAT0) R124.1 U18.7(IO5) ; off-sheet MMC1_DAT0
MMC1_DAT1: J6.8(DAT1) R125.1 U18.6(IO4) ; off-sheet MMC1_DAT1
MMC1_DAT2: J6.1(DAT2) R120.1 U18.3(IO3) ; off-sheet MMC1_DAT2
MMC1_DAT3: J6.2(CD/DAT3) R121.1 U18.2(IO2) ; off-sheet MMC1_DAT3
NetC204_1: C204.1 R126.2 R127.2
NetC210_1: C210.1 R136.1 R138.2 U20.1(REFIN)
NetR132_2: R132.2 U17.L8(ZQ)
NetR135_1: R135.1 TP1.1 U20.9(PGOOD)

Not connected (* = marked no-connect by the designer): J6 10(CD) 11(SW); R128 7 8 9 10; R130 3 14; U17 J1(NC) J9(NC) L1(NC) L9(NC) M7(NC) T7(NC); U18 4(NC) 9(NC); U19 7(WP)*

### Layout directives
differential pair: DDR_CLK_N, DDR_CLK_P, DDR_DQS0_N, DDR_DQS0_P, DDR_DQS1_N, DDR_DQS1_P

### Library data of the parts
C202 C211 C212 C225-C227 C231 C232 = C1608X5R1E106M080AC: CAP, CERM, 10 µF, 25 V, +/- 20%, X5R, 0603; Manufacturer: TDK; Polarized: N; CompType: Capacitor; Value: 10uF; U/M: EA; Cap_F: 0.00001; Tolerance_%: 20; Value1: Unknown; VDC_V: 25; Value2: 25V; TaMin_C: -55; TaMax_C: 85
C203 C204 C207 C209 = GRM155R71A104KA01D: as C236 on sheet TIDA-00204_revE3_JTAGUSB
C205 = GRM033R71A103KA01D: as C235 on sheet TIDA-00204_revE3_JTAGUSB
C206 = GRM155R71C104KA88D: CAP, CERM, 0.1 µF, 16 V, +/- 10%, X7R, 0402; Manufacturer: MuRata; Polarized: N; CompType: Capacitor; Value: 0.1uF; U/M: EA; Cap_F: 0.0000001; Tolerance_%: 10; Value1: Unknown; VDC_V: 16; Value2: 16V; TaMin_C: -55; TaMax_C: 125
C208 C213-C224 C228-C230 = CL03A104KP3NNNC: CAP, CERM, 0.1 µF, 10 V, +/- 10%, X5R, 0201; Manufacturer: Samsung; Polarized: N; CompType: Capacitor; Value: 0.1uF; U/M: EA; Cap_F: 0.0000001; Tolerance_%: 10; Value1: Unknown; Value2: 10V; TaMin_C: -55; TaMax_C: 85
C210 = GRM033R71C102KA01D: CAP, CERM, 1000 pF, 16 V, +/- 10%, X7R, 0201; Manufacturer: MuRata; Polarized: N; CompType: Capacitor; Value: 1000pF; U/M: EA; Cap_F: 0.000000001; Tolerance_%: 10; Value1: Unknown; VDC_V: 16; Value2: 16V; TaMin_C: -55; TaMax_C: 125
C233 = GRM188R61C475KAAJ: as C234 on sheet TIDA-00204_revE3_JTAGUSB
J6 = 502774-0891: Conncetor, micro SD Card, 1.1 mm, R/A, SMT; Manufacturer: Molex; SymbolCreator: Altium; CompType: Connector; U/M: EA
R120-R125 R131 R135 R137 = CRCW040210K0JNED: as R148 on sheet TIDA-00204_revE3_JTAGUSB
R126 R127 = CRCW040249R9FKED: RES, 49.9, 1%, 0.063 W, 0402; Manufacturer: Vishay-Dale; CompType: Resistor; Value: 49.9; Value_Code: 49R9; Tolerance_%: 1; Power_W: 0.063; Value2: 0.063W; VDC_V: 50; TempCo: 100 ppm/C; EIA_Code: E96; U/M: EA
R128 R130 R133 = EXB-2HV470JV: RES, 47, 5%, 0.0625 W, Resistor Array - 8x1; Manufacturer: Panasonic; SymbolCreator: a0411947; Value: 47; Value_Code: 47R0; Tolerance_%: 5; Power_W: 0.0625; TempCo: 200 ppm/C; EIA_Code: E24; U/M: EA
R129 = CRCW04021K00FKED: RES, 1.00 k, 1%, 0.063 W, 0402; Manufacturer: Vishay-Dale; CompType: Resistor; Value: 1.00k; Res_ohm: 1000; Value_Code: 1k00; Tolerance_%: 1; Power_W: 0.063; Value2: 0.063W; VDC_V: 50; TempCo: 100 ppm/C; EIA_Code: E96; U/M: EA
R132 = CRCW0402240RJNED: RES, 240, 5%, 0.063 W, 0402; Manufacturer: Vishay-Dale; CompType: Resistor; Value: 240; Value_Code: 240R; Tolerance_%: 5; Power_W: 0.063; Value2: 0.063W; VDC_V: 50; TempCo: 200 ppm/C; EIA_Code: E24; U/M: EA
R134 = CRCW040247R0JNED: RES, 47, 5%, 0.063 W, 0402; Manufacturer: Vishay-Dale; CompType: Resistor; Value: 47; Value_Code: 47R0; Tolerance_%: 5; Power_W: 0.063; Value2: 0.063W; VDC_V: 50; TempCo: 200 ppm/C; EIA_Code: E24; U/M: EA
R136 R138 = CRCW040210K0FKED: as R158 on sheet TIDA-00204_revE3_JTAGUSB
TP1 TP2 = SMOX/060/B1LP.R3K: Test Point, Silver, SMD; Manufacturer: Oxley; U/M: EA
U17 = MT41J128M16JT-125K TR: 2GBIT DDR3 SDRAM, 96-FBGA; Manufacturer: Micron Technology; SymbolCreator: Altium
U18 = TPD6E001RSER: Low-Capacitance + / - 15 kV ESD Protection Array for High-Speed Data Interfaces, 6 Channels, -40 to +85 degC, 10-pin UQFN (RSE), Green (RoHS & no Sb/Br); Manufacturer: Texas Instruments; Alternate Manufacturer: None; Alternate PartNumber: Equivalent; 1394 / Firewire: TRUE; Breakdown Voltage(Min)(V): 11; IEC 61000-4-2 Air-Gap(+/- kV): 15; IEC 61000-4-2 Contact(+/- kV): 8; IO Capacitance(Typ)(pF): 1.5; IO Leakage Current(nA): 1; SubFamily: ESD Solution
U19 = CAT24C256WI-GT3: 256 kb I2C CMOS Serial EEPROM, SOIC-8; Manufacturer: ON Semiconductor; SymbolCreator: a0411947
U20 = TPS51200DRCR: Single Output LDO, 3 A, 2.375 to 3.5 V Input, with DDR Termination, 10-pin SON (DRC), -40 to 85 degC, Green (RoHS & no Sb/Br); Manufacturer: Texas Instruments; Alternate Manufacturer: None; Alternate PartNumber: Equivalent; Iout(Max)(A): 3; Iq(Typ)(mA): 0.5; Power Good: TRUE; Rating: Catalog; SubFamily: Single Channel LDO; Vin(Max)(V): 3.5; Vin(Min)(V): 2.3

## Sheet TIDA-00204_revE3_PHY_1.SchDoc: =DocumentName
size 431 x 279 mm; Date: Not shown in title block; ApprovedBy: Not shown in title block; CheckedBy: Not shown in title block; Author: Not shown in title block; CompanyName: Not shown in title block; DrawnBy: K. Mogensen; Engineer: K. Mogensen; Organization: Not shown in title block; Address1: Not shown in title block; Address2: Not shown in title block; Address3: Not shown in title block; Address4: Not shown in title block; DocumentNumber: 3; Revision: Use project parameter SCH_Rev; SheetNumber: 3; SheetTotal: 10; PageSetup: Record=PageOptions¦CenterHorizontal=True¦CenterVertical=True¦PrintScale=0.62¦XCorrection=1.00¦YCorrection=1.00¦PrintKind=0¦BorderSize=5000000¦LeftOffset=0¦BottomOffset=0¦Orientation=2¦PaperLength=1000¦PaperWidth=1000¦Scale=100¦PaperSource=15¦PrintQuality=600¦MediaType=1¦DitherType=10¦PrintScaleMode=1¦PaperKind=Letter
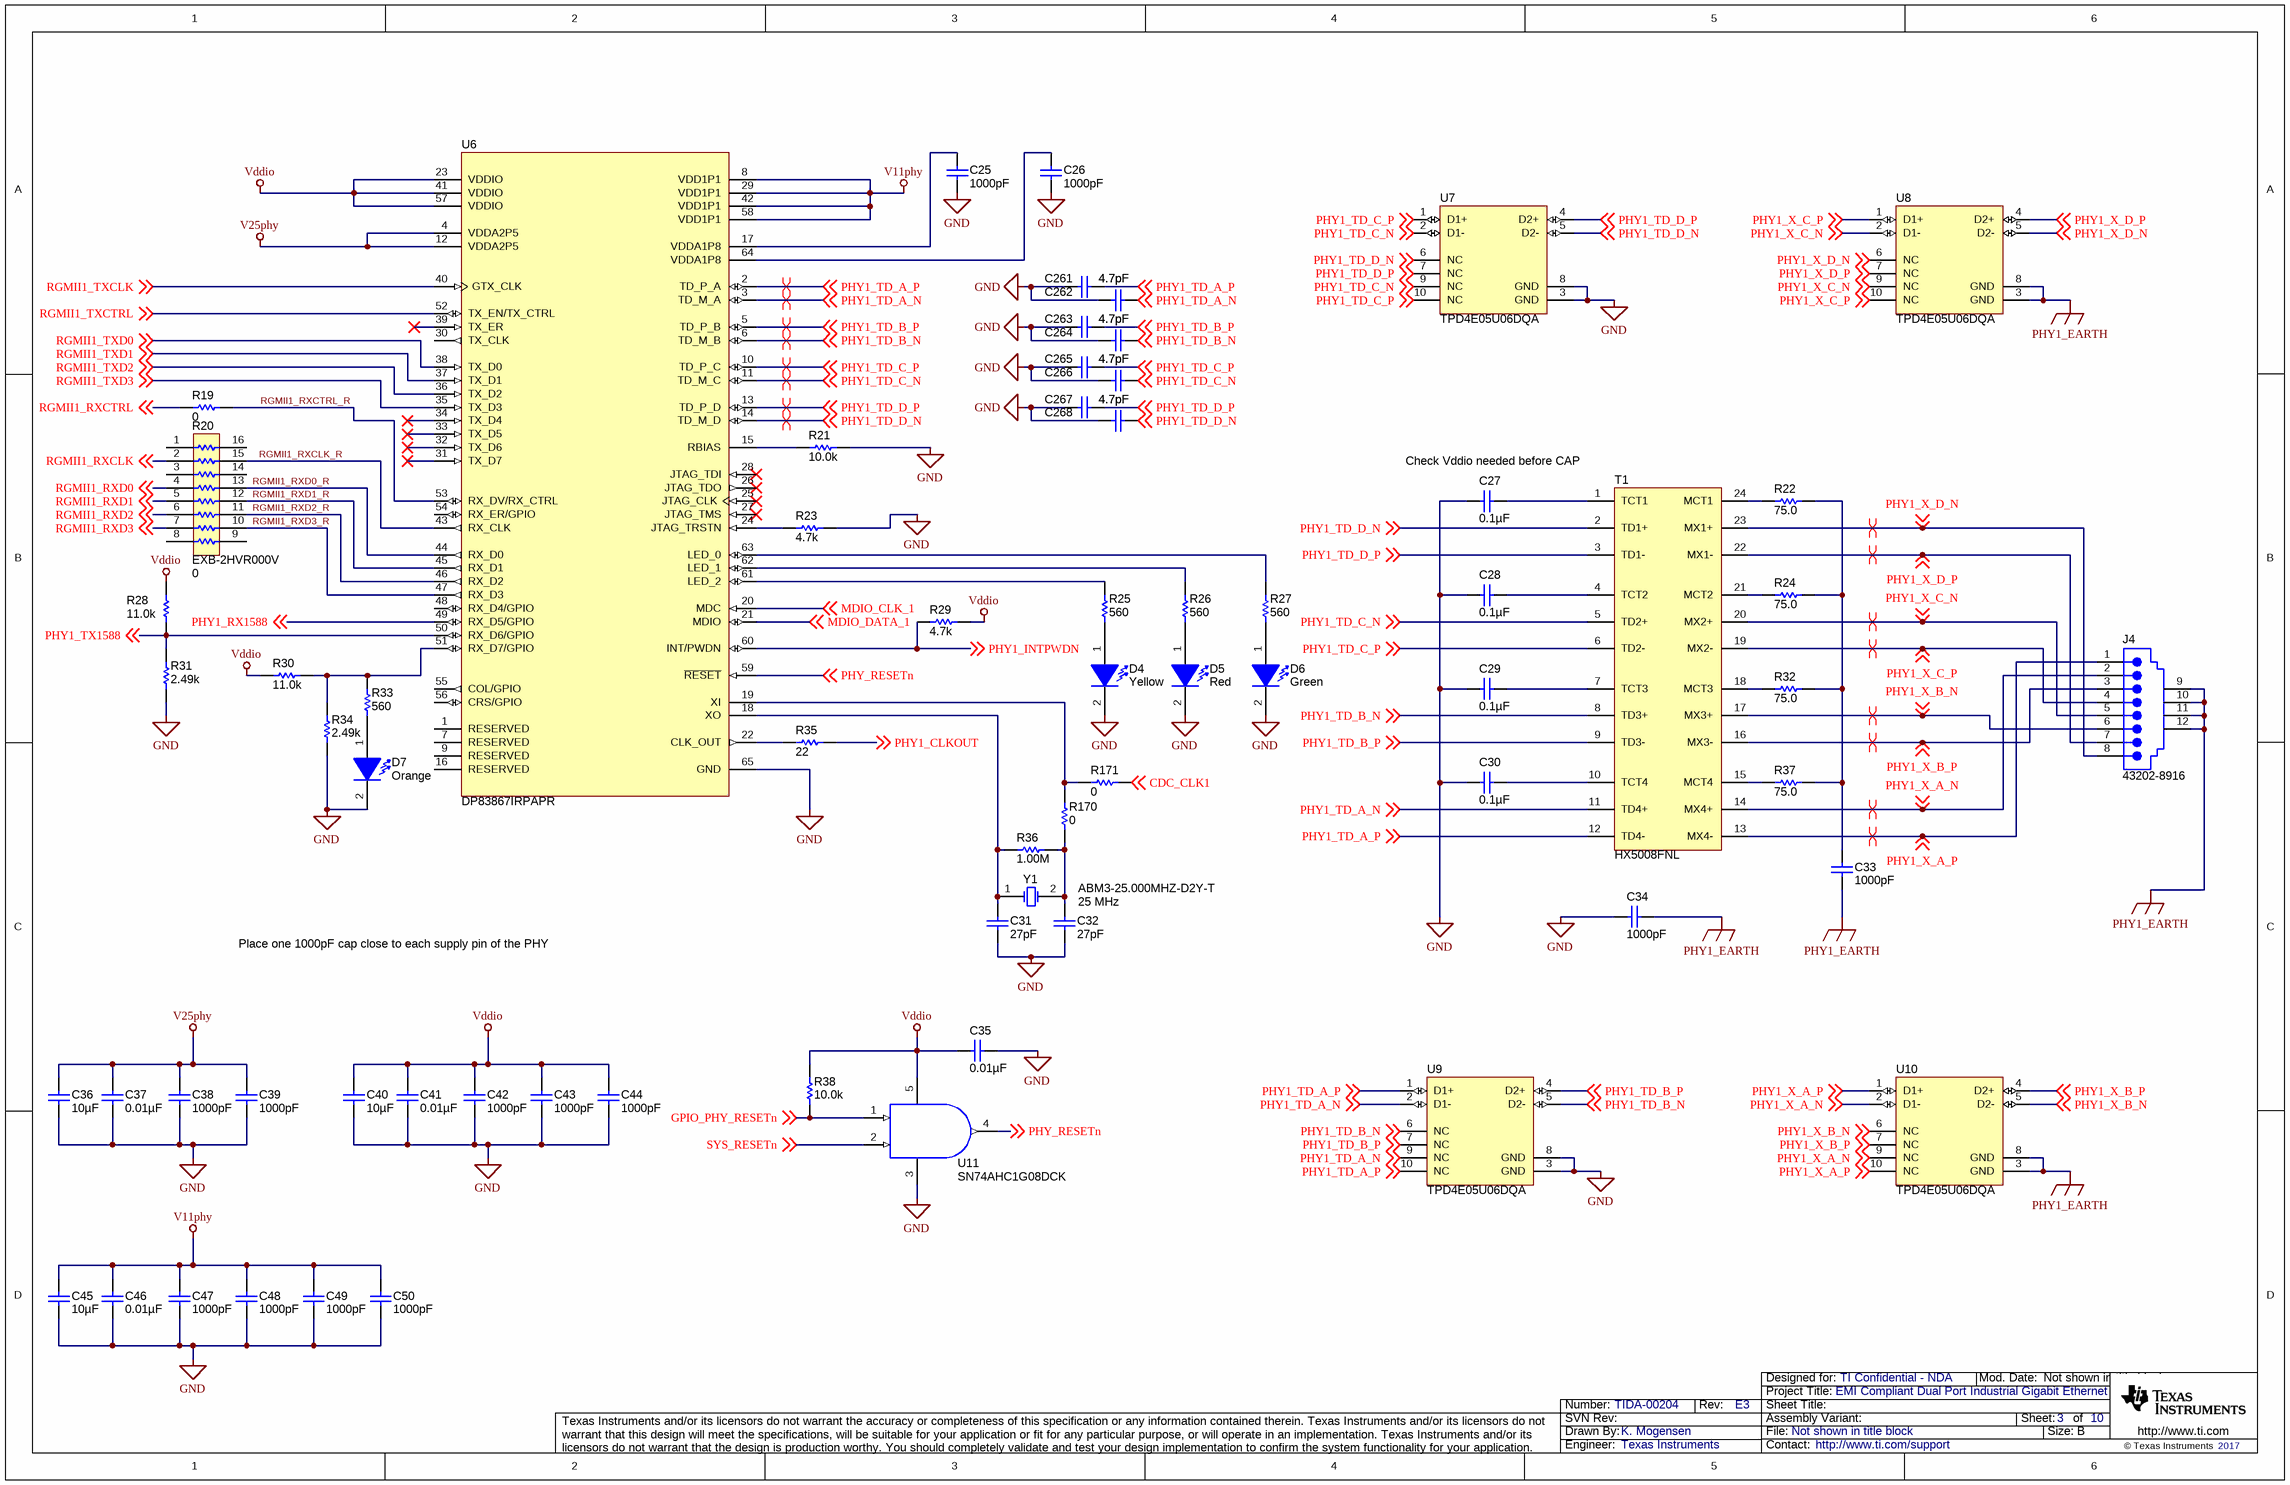
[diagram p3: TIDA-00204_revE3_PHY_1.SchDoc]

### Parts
C25  ValueDisplayed: 1000pF  [0201]  (hidden comment: GRM033R71C102KA01D)
C26  ValueDisplayed: 1000pF  [0201]  (hidden comment: GRM033R71C102KA01D)
C27  ValueDisplayed: 0.1µF  [0402]  (hidden comment: GRM155R71C104KA88D)
C28  ValueDisplayed: 0.1µF  [0402]  (hidden comment: GRM155R71C104KA88D)
C29  ValueDisplayed: 0.1µF  [0402]  (hidden comment: GRM155R71C104KA88D)
C30  ValueDisplayed: 0.1µF  [0402]  (hidden comment: GRM155R71C104KA88D)
C31  ValueDisplayed: 27pF  [0402]  (hidden comment: GRM1555C1H270JA01D)
C32  ValueDisplayed: 27pF  [0402]  (hidden comment: GRM1555C1H270JA01D)
C33  ValueDisplayed: 1000pF  [1206_190]  (hidden comment: 202R18W102KV4E)
C34  ValueDisplayed: 1000pF  [1812]  (hidden comment: 1812GC102KA1)
C35  ValueDisplayed: 0.01µF  [0201]  (hidden comment: GRM033R71A103KA01D)
C36  ValueDisplayed: 10µF  [0603]  (hidden comment: C1608X5R1E106M080AC)
C37  ValueDisplayed: 0.01µF  [0201]  (hidden comment: GRM033R71A103KA01D)
C38  ValueDisplayed: 1000pF  [0201]  (hidden comment: GRM033R71C102KA01D)
C39  ValueDisplayed: 1000pF  [0201]  (hidden comment: GRM033R71C102KA01D)
C40  ValueDisplayed: 10µF  [0603]  (hidden comment: C1608X5R1E106M080AC)
C41  ValueDisplayed: 0.01µF  [0201]  (hidden comment: GRM033R71A103KA01D)
C42  ValueDisplayed: 1000pF  [0201]  (hidden comment: GRM033R71C102KA01D)
C43  ValueDisplayed: 1000pF  [0201]  (hidden comment: GRM033R71C102KA01D)
C44  ValueDisplayed: 1000pF  [0201]  (hidden comment: GRM033R71C102KA01D)
C45  ValueDisplayed: 10µF  [0603]  (hidden comment: C1608X5R1E106M080AC)
C46  ValueDisplayed: 0.01µF  [0201]  (hidden comment: GRM033R71A103KA01D)
C47  ValueDisplayed: 1000pF  [0201]  (hidden comment: GRM033R71C102KA01D)
C48  ValueDisplayed: 1000pF  [0201]  (hidden comment: GRM033R71C102KA01D)
C49  ValueDisplayed: 1000pF  [0201]  (hidden comment: GRM033R71C102KA01D)
C50  ValueDisplayed: 1000pF  [0201]  (hidden comment: GRM033R71C102KA01D)
C261  ValueDisplayed: 4.7pF  [0201]  (hidden comment: GRM0335C1H4R7CA01D)
C262  ValueDisplayed: 4.7pF  [0201]  (hidden comment: GRM0335C1H4R7CA01D)
C263  ValueDisplayed: 4.7pF  [0201]  (hidden comment: GRM0335C1H4R7CA01D)
C264  ValueDisplayed: 4.7pF  [0201]  (hidden comment: GRM0335C1H4R7CA01D)
C265  ValueDisplayed: 4.7pF  [0201]  (hidden comment: GRM0335C1H4R7CA01D)
C266  ValueDisplayed: 4.7pF  [0201]  (hidden comment: GRM0335C1H4R7CA01D)
C267  ValueDisplayed: 4.7pF  [0201]  (hidden comment: GRM0335C1H4R7CA01D)
C268  ValueDisplayed: 4.7pF  [0201]  (hidden comment: GRM0335C1H4R7CA01D)
D4  value Yellow  [LY L29K_Yellow]  (hidden comment: LY L29K-J1K2-26-Z)
D5  value Red  [LS L29K_Red]  (hidden comment: LS L29K-G1J2-1-Z)
D6  value Green  [LG L29K_GREEN]  (hidden comment: LG L29K-G2J1-24-Z)
D7  value Orange  [LO L29K_Orange]  (hidden comment: LO L29K-J2L1-24-Z)
J4  43202-8916  [Molex_43202-8916]
R19  ValueDisplayed: 0  [0402]  (hidden comment: CRCW04020000Z0ED)
R20  EXB-2HVR000V  ValueDisplayed: 0  [RESCAXS_EXB-2HV]
R21  ValueDisplayed: 10.0k  [0402]  (hidden comment: CRCW040210K0FKED)
R22  ValueDisplayed: 75.0  [0603]  (hidden comment: CRCW060375R0FKEA)
R23  ValueDisplayed: 4.7k  [0402]  (hidden comment: CRCW04024K70JNED)
R24  ValueDisplayed: 75.0  [0603]  (hidden comment: CRCW060375R0FKEA)
R25  ValueDisplayed: 560  [0402]  (hidden comment: CRCW0402560RJNED)
R26  ValueDisplayed: 560  [0402]  (hidden comment: CRCW0402560RJNED)
R27  ValueDisplayed: 560  [0402]  (hidden comment: CRCW0402560RJNED)
R28  ValueDisplayed: 11.0k  [0402]  (hidden comment: CRCW040211K0FKED)
R29  ValueDisplayed: 4.7k  [0402]  (hidden comment: CRCW04024K70JNED)
R30  ValueDisplayed: 11.0k  [0402]  (hidden comment: CRCW040211K0FKED)
R31  ValueDisplayed: 2.49k  [0402]  (hidden comment: CRCW04022K49FKED)
R32  ValueDisplayed: 75.0  [0603]  (hidden comment: CRCW060375R0FKEA)
R33  ValueDisplayed: 560  [0402]  (hidden comment: CRCW0402560RJNED)
R34  ValueDisplayed: 2.49k  [0402]  (hidden comment: CRCW04022K49FKED)
R35  ValueDisplayed: 22  [0402]  (hidden comment: CRCW040222R0JNED)
R36  ValueDisplayed: 1.00M  [0402]  (hidden comment: CRCW04021M00FKED)
R37  ValueDisplayed: 75.0  [0603]  (hidden comment: CRCW060375R0FKEA)
R38  ValueDisplayed: 10.0k  [0402]  (hidden comment: CRCW040210K0FKED)
R170  ValueDisplayed: 0  [0402]  (hidden comment: CRCW04020000Z0ED)
R171  ValueDisplayed: 0  [0402]  (hidden comment: CRCW04020000Z0ED)
T1  HX5008FNL  [PULSE_HX5008FNL]
U6  DP83867IRPAPR  [PAP0064M_N]
U7  TPD4E05U06DQA  [DQA0010A]
U8  TPD4E05U06DQA  [DQA0010A]
U9  TPD4E05U06DQA  [DQA0010A]
U10  TPD4E05U06DQA  [DQA0010A]
U11  SN74AHC1G08DCK  [DCK0005A_N]
Y1  ABM3-25.000MHZ-D2Y-T  Frequency: 25 MHz  [XTAL_ABM3]

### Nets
GND: C25.2 C26.2 C27.2 C28.2 C29.2 C30.2 C31.2 C32.2 C34.2 C35.2 C36.2 C37.2 C38.2 C39.2 C40.2 C41.2 C42.2 C43.2 C44.2 C45.2 C46.2 C47.2 C48.2 C49.2 C50.2 C261.1 C262.1 C263.1 C264.1 C265.1 C266.1 C267.1 C268.1 D4.2(K) D5.2(K) D6.2(K) D7.2(K) R21.1 R23.1 R31.1 R34.1 U6.65(GND) U7.3(GND) U7.8(GND) U9.3(GND) U9.8(GND) U11.3(GND)
PHY1_EARTH: C33.2 C34.1 J4.9 J4.10 J4.11 J4.12 U8.3(GND) U8.8(GND) U10.3(GND) U10.8(GND)
V11phy: C45.1 C46.1 C47.1 C48.1 C49.1 C50.1 U6.8(VDD1P1) U6.29(VDD1P1) U6.42(VDD1P1) U6.58(VDD1P1)
V25phy: C36.1 C37.1 C38.1 C39.1 U6.4(VDDA2P5) U6.12(VDDA2P5)
Vddio: C35.1 C40.1 C41.1 C42.1 C43.1 C44.1 R28.1 R29.1 R30.2 R38.2 U6.23(VDDIO) U6.41(VDDIO) U6.57(VDDIO) U11.5(VCC)
CDC_CLK1: R171.2 ; off-sheet CDC_CLK1
GPIO_PHY_RESETn: R38.1 U11.1(A) ; off-sheet GPIO_PHY_RESETn
MDIO_CLK_1: U6.20(MDC) ; off-sheet MDIO_CLK_1
MDIO_DATA_1: U6.21(MDIO) ; off-sheet MDIO_DATA_1
PHY1_CLKOUT: R35.2 ; off-sheet PHY1_CLKOUT
PHY1_INTPWDN: R29.2 U6.60(INT/PWDN) ; off-sheet PHY1_INTPWDN
PHY1_RX1588: U6.49(RX_D5/GPIO) ; off-sheet PHY1_RX1588
PHY1_TD_A_N: C262.2 T1.11(TD4+) U6.3(TD_M_A) U9.2(D1-) U9.9(NC) ; off-sheet PHY1_TD_A_N
PHY1_TD_A_P: C261.2 T1.12(TD4-) U6.2(TD_P_A) U9.1(D1+) U9.10(NC) ; off-sheet PHY1_TD_A_P
PHY1_TD_B_N: C264.2 T1.8(TD3+) U6.6(TD_M_B) U9.5(D2-) U9.6(NC) ; off-sheet PHY1_TD_B_N
PHY1_TD_B_P: C263.2 T1.9(TD3-) U6.5(TD_P_B) U9.4(D2+) U9.7(NC) ; off-sheet PHY1_TD_B_P
PHY1_TD_C_N: C266.2 T1.5(TD2+) U6.11(TD_M_C) U7.2(D1-) U7.9(NC) ; off-sheet PHY1_TD_C_N
PHY1_TD_C_P: C265.2 T1.6(TD2-) U6.10(TD_P_C) U7.1(D1+) U7.10(NC) ; off-sheet PHY1_TD_C_P
PHY1_TD_D_N: C268.2 T1.2(TD1+) U6.14(TD_M_D) U7.5(D2-) U7.6(NC) ; off-sheet PHY1_TD_D_N
PHY1_TD_D_P: C267.2 T1.3(TD1-) U6.13(TD_P_D) U7.4(D2+) U7.7(NC) ; off-sheet PHY1_TD_D_P
PHY1_TX1588: R28.2 R31.2 U6.50(RX_D6/GPIO) ; off-sheet PHY1_TX1588
PHY1_X_A_N: J4.2 T1.14(MX4+) U10.2(D1-) U10.9(NC) ; off-sheet PHY1_X_A_N
PHY1_X_A_P: J4.1 T1.13(MX4-) U10.1(D1+) U10.10(NC) ; off-sheet PHY1_X_A_P
PHY1_X_B_N: J4.6 T1.17(MX3+) U10.5(D2-) U10.6(NC) ; off-sheet PHY1_X_B_N
PHY1_X_B_P: J4.3 T1.16(MX3-) U10.4(D2+) U10.7(NC) ; off-sheet PHY1_X_B_P
PHY1_X_C_N: J4.5 T1.20(MX2+) U8.2(D1-) U8.9(NC) ; off-sheet PHY1_X_C_N
PHY1_X_C_P: J4.4 T1.19(MX2-) U8.1(D1+) U8.10(NC) ; off-sheet PHY1_X_C_P
PHY1_X_D_N: J4.8 T1.23(MX1+) U8.5(D2-) U8.6(NC) ; off-sheet PHY1_X_D_N
PHY1_X_D_P: J4.7 T1.22(MX1-) U8.4(D2+) U8.7(NC) ; off-sheet PHY1_X_D_P
PHY_RESETn: U6.59(~{RESET}) U11.4(Y) ; off-sheet PHY_RESETn
RGMII1_RXCLK: R20.2 ; off-sheet RGMII1_RXCLK
RGMII1_RXCLK_R: R20.15 U6.43(RX_CLK)
RGMII1_RXCTRL: R19.1 ; off-sheet RGMII1_RXCTRL
RGMII1_RXCTRL_R: R19.2 U6.53(RX_DV/RX_CTRL)
RGMII1_RXD0: R20.4 ; off-sheet RGMII1_RXD0
RGMII1_RXD0_R: R20.13 U6.44(RX_D0)
RGMII1_RXD1: R20.5 ; off-sheet RGMII1_RXD1
RGMII1_RXD1_R: R20.12 U6.45(RX_D1)
RGMII1_RXD2: R20.6 ; off-sheet RGMII1_RXD2
RGMII1_RXD2_R: R20.11 U6.46(RX_D2)
RGMII1_RXD3: R20.7 ; off-sheet RGMII1_RXD3
RGMII1_RXD3_R: R20.10 U6.47(RX_D3)
RGMII1_TXCLK: U6.40(GTX_CLK) ; off-sheet RGMII1_TXCLK
RGMII1_TXCTRL: U6.52(TX_EN/TX_CTRL) ; off-sheet RGMII1_TXCTRL
RGMII1_TXD0: U6.38(TX_D0) ; off-sheet RGMII1_TXD0
RGMII1_TXD1: U6.37(TX_D1) ; off-sheet RGMII1_TXD1
RGMII1_TXD2: U6.36(TX_D2) ; off-sheet RGMII1_TXD2
RGMII1_TXD3: U6.35(TX_D3) ; off-sheet RGMII1_TXD3
SYS_RESETn: U11.2(B) ; off-sheet SYS_RESETn
NetC25_1: C25.1 U6.17(VDDA1P8)
NetC26_1: C26.1 U6.64(VDDA1P8)
NetC27_1: C27.1 T1.1(TCT1)
NetC28_1: C28.1 T1.4(TCT2)
NetC29_1: C29.1 T1.7(TCT3)
NetC30_1: C30.1 T1.10(TCT4)
NetC31_1: C31.1 R36.1 U6.18(XO) Y1.1(OSC1)
NetC32_1: C32.1 R36.2 R170.1 Y1.2(OSC2)
NetC33_1: C33.1 R22.2 R24.2 R32.2 R37.2
NetD4_1: D4.1(A) R25.1
NetD5_1: D5.1(A) R26.1
NetD6_1: D6.1(A) R27.1
NetD7_1: D7.1(A) R33.2
NetR21_2: R21.2 U6.15(RBIAS)
NetR22_1: R22.1 T1.24(MCT1)
NetR23_2: R23.2 U6.24(JTAG_TRSTN)
NetR24_1: R24.1 T1.21(MCT2)
NetR25_2: R25.2 U6.61(LED_2)
NetR26_2: R26.2 U6.62(LED_1)
NetR27_2: R27.2 U6.63(LED_0)
NetR30_1: R30.1 R33.1 R34.2 U6.51(RX_D7/GPIO)
NetR32_1: R32.1 T1.18(MCT3)
NetR35_1: R35.1 U6.22(CLK_OUT)
NetR37_1: R37.1 T1.15(MCT4)
NetR170_2: R170.2 R171.1 U6.19(XI)

Not connected (* = marked no-connect by the designer): R20 1 3 8 9 14 16; U6 1(RESERVED) 7(RESERVED) 9(RESERVED) 16(RESERVED) 25(JTAG_CLK)* 26(JTAG_TDO)* 27(JTAG_TMS)* 28(JTAG_TDI)* 30(TX_CLK) 31(TX_D7)* 32(TX_D6)* 33(TX_D5)* 34(TX_D4)* 39(TX_ER)* 48(RX_D4/GPIO) 54(RX_ER/GPIO) 55(COL/GPIO) 56(CRS/GPIO)

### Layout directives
differential pair: PHY1_TD_A_N, PHY1_TD_A_P, PHY1_TD_B_N, PHY1_TD_B_P, PHY1_TD_C_N, PHY1_TD_C_P, PHY1_TD_D_N, PHY1_TD_D_P, PHY1_X_A_N, PHY1_X_A_P, PHY1_X_B_N, PHY1_X_B_P, PHY1_X_C_N, PHY1_X_C_P, PHY1_X_D_N, PHY1_X_D_P

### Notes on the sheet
- Check Vddio needed before CAP
- Place one 1000pF cap close to each supply pin of the PHY

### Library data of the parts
C25 C26 C38 C39 C42-C44 C47-C50 = GRM033R71C102KA01D: as C210 on sheet TIDA-00204_revE3_Memory
C27-C30 = GRM155R71C104KA88D: as C206 on sheet TIDA-00204_revE3_Memory
C31 C32 = GRM1555C1H270JA01D: as C240 on sheet TIDA-00204_revE3_JTAGUSB
C33 = 202R18W102KV4E: CAP, CERM, 1000 pF, 2000 V, +/- 10%, X7R, 1206_190; Manufacturer: Johanson Technology; Polarized: N; CompType: Capacitor; Value: 1000pF; U/M: EA; Cap_F: 0.000000001; Tolerance_%: 10; Value1: Unknown; VDC_V: 2000; Value2: 2000V; TaMin_C: -55; TaMax_C: 125
C34 = 1812GC102KA1: CAP, CERM, 1000 pF, 2000 V, +/- 10%, X7R, 1812; Manufacturer: AVX; Polarized: N; CompType: Capacitor; Value: 1000pF; U/M: EA; Cap_F: 0.000000001; Tolerance_%: 10; Value1: Unknown; VDC_V: 2000; Value2: 2000V; TaMin_C: -55; TaMax_C: 125
C35 C37 C41 C46 = GRM033R71A103KA01D: as C235 on sheet TIDA-00204_revE3_JTAGUSB
C36 C40 C45 = C1608X5R1E106M080AC: as C202 on sheet TIDA-00204_revE3_Memory
C261-C268 = GRM0335C1H4R7CA01D: CAP, CERM, 4.7 pF, 50 V, +/- 5%, C0G/NP0, 0201; Manufacturer: MuRata; Polarized: N; CompType: Capacitor; Value: 4.7pF; U/M: EA; Cap_F: 0.0000000000047; Tolerance_%: 5; Value1: Unknown; VDC_V: 50; Value2: 50V; TaMin_C: -55; TaMax_C: 125
D4 = LY L29K-J1K2-26-Z: LED, Yellow, SMD; Manufacturer: OSRAM; Vf_V: 1.8; Value2: 1.8V; Io_A: 0.002; Tjmax_C: 110; Value1: W; U/M: EA
D5 = LS L29K-G1J2-1-Z: LED, Red, SMD; Manufacturer: OSRAM; Vf_V: 1.8; Value2: 1.8V; Io_A: 0.02; Vr_V: 12; Tjmax_C: 110; Value1: W; Angle: 160; U/M: EA
D6 = LG L29K-G2J1-24-Z: LED, Green, SMD; Manufacturer: OSRAM; Vf_V: 1.7; Value2: 1.7V; Io_A: 0.002; Tjmax_C: 110; Value1: W; U/M: EA
D7 = LO L29K-J2L1-24-Z: LED, Orange, SMD; Manufacturer: OSRAM; Vf_V: 1.8; Value2: 1.8V; Io_A: 0.02; Vr_V: 12; Tjmax_C: 110; Value1: W; Angle: 160; U/M: EA
J4 = 43202-8916: Modular Jack(Shielded), Gold, R/A, TH; Manufacturer: Molex; SymbolCreator: Altium; U/M: EA
R19 R170 R171 = CRCW04020000Z0ED: RES, 0, 5%, 0.063 W, 0402; Manufacturer: Vishay-Dale; CompType: Resistor; Value: 0; Value_Code: 0000; Tolerance_%: 5; Power_W: 0.063; Value2: 0.063W; VDC_V: 50; TempCo: 200 ppm/C; EIA_Code: E24; U/M: EA
R20 = EXB-2HVR000V: RES, 0, 5%, 0.0625 W, Resistor Array - 8x1; Manufacturer: Panasonic; SymbolCreator: a0411947; Value: 0; Value_Code: 0000; Tolerance_%: 5; Power_W: 0.0625; TempCo: ppm/C; EIA_Code: E24; U/M: EA
R21 R38 = CRCW040210K0FKED: as R158 on sheet TIDA-00204_revE3_JTAGUSB
R22 R24 R32 R37 = CRCW060375R0FKEA: RES, 75.0, 1%, 0.1 W, 0603; Manufacturer: Vishay-Dale; CompType: Resistor; Value: 75.0; Res_ohm: 75; Value_Code: 75R0; Tolerance_%: 1; Power_W: 0.1; Value2: 0.1W; TempCo: 100 ppm/C; EIA_Code: E96; U/M: EA
R23 R29 = CRCW04024K70JNED: as R146 on sheet TIDA-00204_revE3_JTAGUSB
R25-R27 R33 = CRCW0402560RJNED: RES, 560, 5%, 0.063 W, 0402; Manufacturer: Vishay-Dale; CompType: Resistor; Value: 560; Value_Code: 560R; Tolerance_%: 5; Power_W: 0.063; Value2: 0.063W; VDC_V: 50; TempCo: 200 ppm/C; EIA_Code: E24; U/M: EA
R28 R30 = CRCW040211K0FKED: RES, 11.0 k, 1%, 0.063 W, 0402; Manufacturer: Vishay-Dale; CompType: Resistor; Value: 11.0k; Res_ohm: 11000; Value_Code: 11k0; Tolerance_%: 1; Power_W: 0.063; Value2: 0.063W; VDC_V: 50; TempCo: 100 ppm/C; EIA_Code: E96; U/M: EA
R31 R34 = CRCW04022K49FKED: RES, 2.49 k, 1%, 0.063 W, 0402; Manufacturer: Vishay-Dale; CompType: Resistor; Value: 2.49k; Res_ohm: 2490; Value_Code: 2k49; Tolerance_%: 1; Power_W: 0.063; Value2: 0.063W; VDC_V: 50; TempCo: 100 ppm/C; EIA_Code: E96; U/M: EA
R35 = CRCW040222R0JNED: RES, 22, 5%, 0.063 W, 0402; Manufacturer: Vishay-Dale; CompType: Resistor; Value: 22; Value_Code: 22R0; Tolerance_%: 5; Power_W: 0.063; Value2: 0.063W; VDC_V: 50; TempCo: 200 ppm/C; EIA_Code: E24; U/M: EA
R36 = CRCW04021M00FKED: RES, 1.00 M, 1%, 0.063 W, 0402; Manufacturer: Vishay-Dale; CompType: Resistor; Value: 1.00Meg; Res_ohm: 1000000; Value_Code: 1M00; Tolerance_%: 1; Power_W: 0.063; Value2: 0.063W; VDC_V: 50; TempCo: 100 ppm/C; EIA_Code: E96; U/M: EA
T1 = HX5008FNL: Transformer, 325 uH, SMT; Manufacturer: Pulse Engineering; SymbolCreator: Altium; Value: 325 uH; U/M: EA
U6 = DP83867IRPAPR: Robust, Low Power 10/100/1000 Ethernet Physical Layer Transceiver, PAP0064M; Alternate PartNumber: DP83867IRPAPT; Manufacturer: Texas Instruments; SymbolCreator: Altium; CompType: IC; U/M: EA
U7-U10 = TPD4E05U06DQA: 1, 4, 6 CHANNEL PROTECTION SOLUTION FOR SUPER-SPEED (UP TO 6 GBPS) INTERFACE, DQA0010A; Alternate Manufacturer: None; Manufacturer: Texas Instruments; SymbolCreator: a0411947; CompType: IC; U/M: EA
U11 = SN74AHC1G08DCK: Single 2-Input Positive-AND Gate, DCK0005A; Alternate Manufacturer: None; Manufacturer: Texas Instruments; SymbolCreator: x0208326; CompType: IC; U/M: EA
Y1 = ABM3-25.000MHZ-D2Y-T: Crystal, 25 MHz, 18 pF, SMD; Manufacturer: Abracon Corportation; SymbolCreator: a0412235; U/M: EA; TaMin_C: -40; TaMax_C: 85; Frequency Stability: ±30ppm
